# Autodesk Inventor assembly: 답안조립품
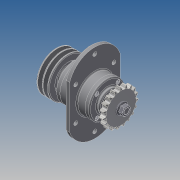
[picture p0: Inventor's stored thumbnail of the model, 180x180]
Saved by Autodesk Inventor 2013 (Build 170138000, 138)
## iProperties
Created: 2015-02
Part Number: 답안조립품
Document SubType Name: Assembly
Designer: kb146
Author: kb146
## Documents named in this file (12)
- C:\Users\kb146\Desktop\450207V1024\답안조립품.iam
- C:\Users\kb146\Desktop\450207V1024\1-본체.ipt
- C:\Users\kb146\Desktop\450207V1024\2-커버.ipt
- C:\Users\kb146\Desktop\450207V1024\3-축.ipt
- C:\Users\kb146\Desktop\450207V1024\4-V벨트풀리.ipt
- C:\Users\kb146\Desktop\450207V1024\5-체인 스프로킷.ipt
- C:\Users\kb146\Desktop\450207V1024\6-베어링 6206.ipt
- C:\Users\kb146\Desktop\450207V1024\7-부시.ipt
- C:\Users\kb146\Desktop\450207V1024\8-오일실 30x42.ipt
- C:\Users\kb146\Desktop\450207V1024\9-M16-너트.ipt
- C:\Users\kb146\Desktop\450207V1024\10-M6.ipt
- C:\Users\kb146\Desktop\450207V1024\11-키 6x6.ipt
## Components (23 placed, 11 different names)
1. 1-본체:1
2. 2-커버:1
3. 3-축:1
4. 4-V벨트풀리:1
5. 5-체인 스프로킷:1
6. 6-베어링 6206:1
7. 7-부시:1
8. 8-8-오일실 30x42:1
9. 9-M16 너트:1
10. 11-키 6x6:1
11. 11-키 6x6:2
12. 2-커버:2
13. 8-8-오일실 30x42:2
14. 6-베어링 6206:2
15. 9-M16 너트:2
16. 10-M6:1
17. 10-M6:3
18. 10-M6:4
19. 10-M6:5
20. 10-M6:2
21. 10-M6:6
22. 10-M6:7
23. 10-M6:8
